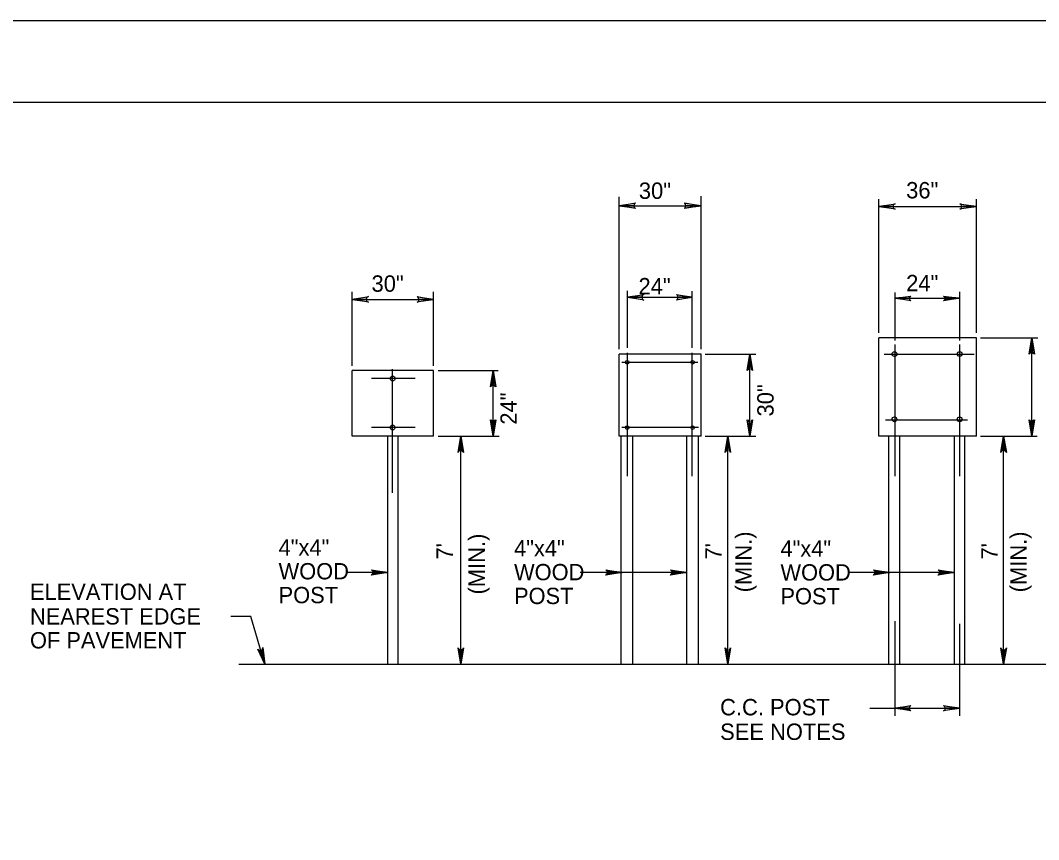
# Model space of a CAD drawing. Extents: x 648590 to 650336, y 294467 to 295061.
# Drawn here: x 648999.2 to 649185.6, y 294911.5 to 295061.4 of the extents above; entities that cross this region are included whole.
import ezdxf

# ---------------------------------------------------------------- set-up
doc = ezdxf.new("R2010")
doc.units = 0
for name, color, linetype in [('1', 7, 'Continuous'), ('2', 7, 'Continuous'), ('3', 7, 'Continuous'), ('PLT-BNDY', 7, 'Continuous')]:
    doc.layers.add(name, color=color, linetype=linetype)

msp = doc.modelspace()

# ---------------------------------------------------------------- linework, layer by layer
at = {"layer": '1'}
msp.add_line((648630.1, 295046.45), (649416.1, 295046.45), dxfattribs=at)
at = {"layer": '2'}
for p, q in [((649108.85, 295001.22), (649108.85, 295029.14)), ((649123.85, 295001.22), (649123.85, 295029.26)), ((649156.35, 295004.22), (649156.35, 295028.74)), ((649174.22, 295004.22), (649174.22, 295028.74)), ((649108.85, 295027.51), (649123.85, 295027.51)), ((649156.35, 295027.37), (649174.22, 295027.37)), ((649110.35, 295009.69), (649110.35, 295011.94)), ((649122.22, 295009.46), (649122.22, 295011.87)), ((649059.97, 294998.22), (649059.97, 295011.74)), ((649059.97, 295010.37), (649074.85, 295010.37)), ((649074.85, 294998.22), (649074.85, 295011.74)), ((649110.35, 295010.74), (649122.22, 295010.74)), ((649159.35, 295009.69), (649159.35, 295011.6)), ((649159.35, 295010.61), (649171.22, 295010.61)), ((649171.22, 295009.69), (649171.22, 295011.73)), ((649110.35, 295001.47), (649110.35, 295009.69)), ((649122.22, 295001.47), (649122.22, 295009.46)), ((649159.35, 295002.84), (649159.35, 295009.69)), ((649171.22, 295002.84), (649171.22, 295009.69)), ((649156.35, 294985.34), (649156.35, 295003.34)), ((649174.22, 295003.34), (649156.35, 295003.34)), ((649174.22, 294985.34), (649174.22, 295003.34)), ((649174.97, 295003.34), (649185.5, 295003.34)), ((649184.38, 294985.34), (649184.38, 295003.34)), ((649159.35, 294977.97), (649159.35, 295002.09)), ((649171.22, 294977.97), (649171.22, 295002.09)), ((649108.85, 294985.34), (649108.85, 295000.34)), ((649123.85, 295000.34), (649108.85, 295000.34)), ((649109.35, 294998.84), (649123.22, 294998.84)), ((649110.35, 294977.97), (649110.35, 295000.59)), ((649110.35, 294998.84), (649110.35, 294998.84)), ((649122.22, 294977.97), (649122.22, 295000.59)), ((649122.22, 294998.84), (649122.22, 294998.84)), ((649123.85, 294985.34), (649123.85, 295000.34)), ((649124.6, 295000.34), (649133.87, 295000.34)), ((649132.74, 294985.34), (649132.74, 295000.34)), ((649157.35, 295000.34), (649173.85, 295000.34)), ((649159.22, 295000.34), (649159.22, 295000.34)), ((649171.22, 295000.34), (649171.22, 295000.34)), ((649059.97, 294985.34), (649059.97, 294997.34)), ((649074.85, 294997.34), (649059.97, 294997.34)), ((649067.35, 294974.97), (649067.35, 294997.59)), ((649074.85, 294985.34), (649074.85, 294997.34)), ((649075.72, 294997.34), (649086.69, 294997.34)), ((649085.75, 294985.34), (649085.75, 294997.34)), ((649063.47, 294995.97), (649071.47, 294995.97)), ((649067.35, 294995.97), (649067.35, 294995.97)), ((649157.6, 294988.34), (649172.6, 294988.34)), ((649158.6, 294988.34), (649158.6, 294988.34)), ((649171.1, 294988.34), (649171.1, 294988.34)), ((649063.47, 294986.97), (649071.47, 294986.97)), ((649067.35, 294986.97), (649067.35, 294986.97)), ((649109.35, 294986.97), (649123.35, 294986.97)), ((649110.35, 294986.97), (649110.35, 294986.97)), ((649122.22, 294986.97), (649122.22, 294986.97)), ((649074.85, 294985.34), (649059.97, 294985.34)), ((649066.47, 294943.59), (649066.47, 294985.34)), ((649068.35, 294943.59), (649068.35, 294985.34)), ((649075.72, 294985.34), (649086.88, 294985.34)), ((649079.85, 294943.59), (649079.85, 294985.34)), ((649123.85, 294985.34), (649108.85, 294985.34)), ((649109.22, 294943.59), (649109.22, 294985.34)), ((649111.35, 294943.59), (649111.35, 294985.34)), ((649121.22, 294943.59), (649121.22, 294985.34)), ((649123.35, 294943.59), (649123.35, 294985.34)), ((649124.6, 294985.34), (649133.87, 294985.34)), ((649128.72, 294943.59), (649128.72, 294985.34)), ((649174.22, 294985.34), (649156.35, 294985.34)), ((649158.22, 294943.59), (649158.22, 294985.34)), ((649160.22, 294943.59), (649160.22, 294985.34)), ((649170.22, 294943.59), (649170.22, 294985.34)), ((649172.1, 294943.59), (649172.1, 294985.34)), ((649174.97, 294985.34), (649185.38, 294985.34)), ((649179.22, 294943.59), (649179.22, 294985.34)), ((649066.47, 294960.36), (649058.8, 294960.36)), ((649121.22, 294960.36), (649101.71, 294960.36)), ((649170.22, 294960.36), (649150.71, 294960.36)), ((649041.42, 294952.31), (649037.72, 294952.31)), ((649043.97, 294943.59), (649041.42, 294952.31)), ((649159.35, 294934.15), (649159.35, 294951.47)), ((649171.22, 294934.15), (649171.22, 294950.97)), ((649039.22, 294943.59), (649407.82, 294943.59)), ((649154.72, 294935.53), (649171.22, 294935.53))]:
    msp.add_line(p, q, dxfattribs=at)
for points in [[(649111.72, 295027.14), (649111.6, 295027.39), (649108.85, 295027.51), (649111.72, 295027.14), (649111.85, 295027.01), (649108.85, 295027.51), (649111.6, 295027.64), (649111.72, 295027.89), (649108.85, 295027.51), (649111.85, 295028.01), (649111.72, 295027.89)], [(649120.85, 295027.89), (649120.97, 295027.64), (649123.85, 295027.51), (649120.85, 295027.89), (649120.85, 295028.01), (649123.85, 295027.51), (649120.97, 295027.39), (649120.85, 295027.14), (649123.85, 295027.51), (649120.85, 295027.01), (649120.85, 295027.14)], [(649159.1, 295026.99), (649158.97, 295027.24), (649156.35, 295027.37), (649159.1, 295026.99), (649159.35, 295026.87), (649156.35, 295027.37), (649158.97, 295027.49), (649159.1, 295027.74), (649156.35, 295027.37), (649159.35, 295027.87), (649159.1, 295027.74)], [(649171.35, 295027.74), (649171.47, 295027.49), (649174.22, 295027.37), (649171.35, 295027.74), (649171.22, 295027.87), (649174.22, 295027.37), (649171.47, 295027.24), (649171.35, 295026.99), (649174.22, 295027.37), (649171.22, 295026.87), (649171.35, 295026.99)], [(649062.72, 295009.99), (649062.6, 295010.24), (649059.97, 295010.37), (649062.72, 295009.99), (649062.97, 295009.87), (649059.97, 295010.37), (649062.6, 295010.49), (649062.72, 295010.74), (649059.97, 295010.37), (649062.97, 295010.87), (649062.72, 295010.74)], [(649071.97, 295010.74), (649072.1, 295010.49), (649074.85, 295010.37), (649071.97, 295010.74), (649071.85, 295010.87), (649074.85, 295010.37), (649072.1, 295010.24), (649072.1, 295009.99), (649074.85, 295010.37), (649071.85, 295009.87), (649072.1, 295009.99)], [(649113.1, 295010.37), (649113.1, 295010.62), (649110.35, 295010.74), (649113.1, 295010.37), (649113.35, 295010.24), (649110.35, 295010.74), (649113.1, 295010.87), (649113.1, 295011.12), (649110.35, 295010.74), (649113.35, 295011.24), (649113.1, 295011.12)], [(649119.47, 295011.12), (649119.6, 295010.87), (649122.22, 295010.74), (649119.47, 295011.12), (649119.35, 295011.24), (649122.22, 295010.74), (649119.6, 295010.62), (649119.47, 295010.37), (649122.22, 295010.74), (649119.35, 295010.24), (649119.47, 295010.37)], [(649162.1, 295010.23), (649161.97, 295010.48), (649159.35, 295010.61), (649162.1, 295010.23), (649162.22, 295010.11), (649159.35, 295010.61), (649161.97, 295010.61), (649162.1, 295010.86), (649159.35, 295010.61), (649162.22, 295010.98), (649162.1, 295010.86)], [(649168.35, 295010.86), (649168.47, 295010.73), (649171.22, 295010.61), (649168.35, 295010.86), (649168.22, 295010.98), (649171.22, 295010.61), (649168.47, 295010.48), (649168.47, 295010.36), (649171.22, 295010.61), (649168.22, 295010.11), (649168.47, 295010.36)], [(649184, 295000.47), (649184.13, 295000.59), (649184.38, 295003.34), (649184, 295000.47), (649183.88, 295000.34), (649184.38, 295003.34), (649184.5, 295000.59), (649184.63, 295000.47), (649184.38, 295003.34), (649184.88, 295000.34), (649184.63, 295000.47)], [(649132.37, 294997.47), (649132.62, 294997.59), (649132.74, 295000.34), (649132.37, 294997.47), (649132.24, 294997.34), (649132.74, 295000.34), (649132.99, 294997.59), (649133.12, 294997.47), (649132.74, 295000.34), (649133.24, 294997.34), (649133.12, 294997.47)], [(649085.38, 294994.47), (649085.5, 294994.59), (649085.75, 294997.34), (649085.38, 294994.47), (649085.25, 294994.34), (649085.75, 294997.34), (649085.88, 294994.59), (649086, 294994.47), (649085.75, 294997.34), (649086.25, 294994.34), (649086, 294994.47)], [(649086.13, 294988.22), (649085.88, 294988.09), (649085.75, 294985.34), (649086.13, 294988.22), (649086.25, 294988.34), (649085.75, 294985.34), (649085.63, 294988.09), (649085.38, 294988.22), (649085.75, 294985.34), (649085.25, 294988.34), (649085.38, 294988.22)], [(649133.12, 294988.22), (649132.99, 294988.09), (649132.74, 294985.34), (649133.12, 294988.22), (649133.24, 294988.34), (649132.74, 294985.34), (649132.62, 294988.09), (649132.49, 294988.22), (649132.74, 294985.34), (649132.24, 294988.34), (649132.49, 294988.22)], [(649184.75, 294988.22), (649184.5, 294988.09), (649184.38, 294985.34), (649184.75, 294988.22), (649184.88, 294988.34), (649184.38, 294985.34), (649184.13, 294988.09), (649184, 294988.22), (649184.38, 294985.34), (649183.88, 294988.34), (649184, 294988.22)], [(649079.47, 294982.59), (649079.6, 294982.72), (649079.85, 294985.34), (649079.47, 294982.59), (649079.35, 294982.34), (649079.85, 294985.34), (649079.97, 294982.72), (649080.1, 294982.59), (649079.85, 294985.34), (649080.35, 294982.34), (649080.1, 294982.59)], [(649128.35, 294982.59), (649128.6, 294982.72), (649128.72, 294985.34), (649128.35, 294982.59), (649128.22, 294982.34), (649128.72, 294985.34), (649128.97, 294982.72), (649129.1, 294982.59), (649128.72, 294985.34), (649129.22, 294982.34), (649129.1, 294982.59)], [(649178.85, 294982.59), (649178.97, 294982.72), (649179.22, 294985.34), (649178.85, 294982.59), (649178.72, 294982.34), (649179.22, 294985.34), (649179.35, 294982.72), (649179.47, 294982.59), (649179.22, 294985.34), (649179.72, 294982.34), (649179.47, 294982.59)], [(649063.6, 294960.74), (649063.72, 294960.61), (649066.47, 294960.36), (649063.6, 294960.74), (649063.47, 294960.86), (649066.47, 294960.36), (649063.72, 294960.24), (649063.6, 294960.11), (649066.47, 294960.36), (649063.47, 294959.86), (649063.6, 294960.11)], [(649106.51, 294960.74), (649106.63, 294960.61), (649109.38, 294960.36), (649106.51, 294960.74), (649106.38, 294960.86), (649109.38, 294960.36), (649106.63, 294960.24), (649106.51, 294960.11), (649109.38, 294960.36), (649106.38, 294959.86), (649106.51, 294960.11)], [(649118.35, 294960.74), (649118.47, 294960.61), (649121.22, 294960.36), (649118.35, 294960.74), (649118.22, 294960.86), (649121.22, 294960.36), (649118.47, 294960.24), (649118.35, 294960.11), (649121.22, 294960.36), (649118.22, 294959.86), (649118.35, 294960.11)], [(649155.51, 294960.74), (649155.63, 294960.61), (649158.38, 294960.36), (649155.51, 294960.74), (649155.38, 294960.86), (649158.38, 294960.36), (649155.63, 294960.24), (649155.51, 294960.11), (649158.38, 294960.36), (649155.38, 294959.86), (649155.51, 294960.11)], [(649167.35, 294960.74), (649167.47, 294960.61), (649170.22, 294960.36), (649167.35, 294960.74), (649167.22, 294960.86), (649170.22, 294960.36), (649167.47, 294960.24), (649167.35, 294960.11), (649170.22, 294960.36), (649167.22, 294959.86), (649167.35, 294960.11)], [(649043.57, 294946.34), (649043.36, 294946.15), (649043.97, 294943.59), (649043.57, 294946.34), (649043.62, 294946.61), (649043.97, 294943.59), (649043.12, 294946.08), (649042.85, 294946.13), (649043.97, 294943.59), (649042.66, 294946.34), (649042.85, 294946.13)], [(649080.22, 294946.34), (649079.97, 294946.22), (649079.85, 294943.59), (649080.22, 294946.34), (649080.35, 294946.59), (649079.85, 294943.59), (649079.72, 294946.22), (649079.47, 294946.34), (649079.85, 294943.59), (649079.35, 294946.59), (649079.47, 294946.34)], [(649129.1, 294946.34), (649128.97, 294946.22), (649128.72, 294943.59), (649129.1, 294946.34), (649129.22, 294946.59), (649128.72, 294943.59), (649128.6, 294946.22), (649128.47, 294946.34), (649128.72, 294943.59), (649128.22, 294946.59), (649128.47, 294946.34)], [(649179.6, 294946.34), (649179.35, 294946.22), (649179.22, 294943.59), (649179.6, 294946.34), (649179.72, 294946.59), (649179.22, 294943.59), (649178.97, 294946.22), (649178.85, 294946.34), (649179.22, 294943.59), (649178.72, 294946.59), (649178.85, 294946.34)], [(649162.1, 294935.15), (649161.97, 294935.28), (649159.35, 294935.53), (649162.1, 294935.15), (649162.22, 294935.03), (649159.35, 294935.53), (649161.97, 294935.65), (649162.1, 294935.9), (649159.35, 294935.53), (649162.22, 294936.03), (649162.1, 294935.9)], [(649168.35, 294935.9), (649168.47, 294935.65), (649171.22, 294935.53), (649168.35, 294935.9), (649168.22, 294936.03), (649171.22, 294935.53), (649168.47, 294935.4), (649168.47, 294935.15), (649171.22, 294935.53), (649168.22, 294935.03), (649168.47, 294935.15)]]:
    msp.add_lwpolyline(points, dxfattribs=at)
for centre, radius in [((649159.23, 295000.35), 0.441), ((649171.17, 295000.37), 0.441), ((649110.31, 294998.86), 0.331), ((649122.28, 294998.85), 0.331), ((649067.37, 294995.88), 0.441), ((649159.22, 294988.41), 0.441), ((649171.17, 294988.4), 0.441), ((649067.36, 294986.9), 0.441), ((649110.31, 294986.9), 0.331), ((649122.28, 294986.9), 0.331)]:
    msp.add_circle(centre, radius, dxfattribs=at)
at = {"layer": 'PLT-BNDY'}
msp.add_lwpolyline([(648590.1, 295061.45), (649431.1, 295061.45), (649431.1, 294467.45), (648590.1, 294467.45)], close=True, dxfattribs=at)

# ---------------------------------------------------------------- texts
at = {"layer": '3'}
for s, height, p in [('30"', 3, (649112.44, 295028.76)), ('36"', 3, (649161.37, 295028.85)), ('30"', 3, (649063.5, 295011.76)), ('24"', 3, (649112.37, 295011.28)), ('24"', 3, (649161.37, 295011.85)), ('4"x4"', 2.988, (649046.49, 294963.47)), ('4"x4"', 2.988, (649089.59, 294963.3)), ('4"x4"', 2.988, (649138.36, 294963.25)), ('WOOD', 2.988, (649046.49, 294959.1)), ('WOOD', 2.988, (649089.59, 294958.94)), ('WOOD', 2.988, (649138.36, 294958.89)), ('ELEVATION AT', 2.988, (649000.98, 294955.34)), ('POST', 2.988, (649046.49, 294954.74)), ('POST', 2.988, (649089.59, 294954.58)), ('POST', 2.988, (649138.36, 294954.53)), ('NEAREST EDGE', 2.988, (649000.98, 294950.84)), ('OF PAVEMENT', 2.988, (649000.98, 294946.46)), ('C.C. POST', 3, (649127.31, 294934.21)), ('SEE NOTES', 3, (649127.31, 294929.71))]:
    msp.add_text(s, height=height, dxfattribs=at).set_placement(p)
for s, p in [('24"', (649090.1, 294987.43)), ('30"', (649137.11, 294988.93)), ('(MIN.)', (649084.25, 294956.34)), ('(MIN.)', (649133.11, 294956.73)), ('(MIN.)', (649183.43, 294956.73)), ("7'", (649078.39, 294962.73)), ("7'", (649127.59, 294962.73)), ("7'", (649178.14, 294962.73))]:
    msp.add_text(s, height=3, rotation=90, dxfattribs=at).set_placement(p)

doc.saveas('drawing.dxf')
